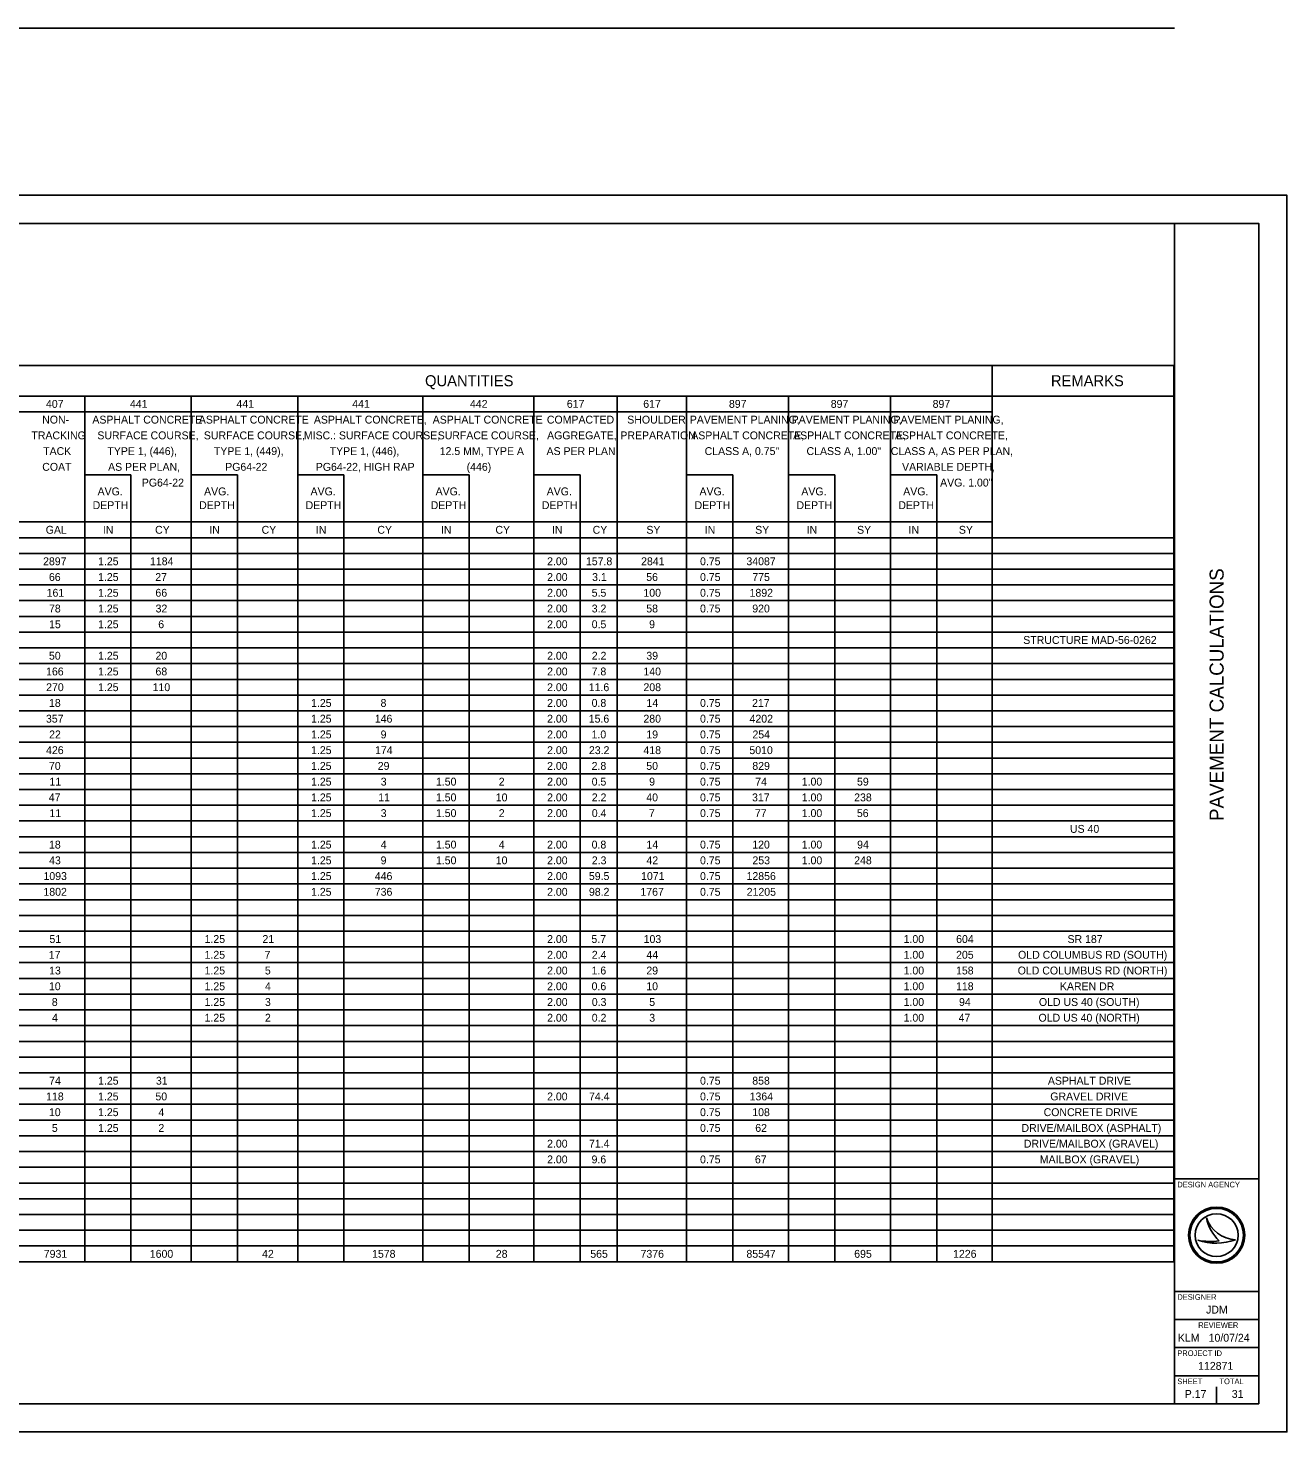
# Model space of a CAD drawing. Extents: x -2.5 to 34, y 0 to 25.
# Drawn here: x 11.61 to 34, y 0 to 24.97 of the extents above; entities that cross this region are included whole.
import ezdxf

# ---------------------------------------------------------------- set-up
doc = ezdxf.new("R2010")
doc.units = 0
for name, color, linetype in [('SH_Border', 7, 'Continuous'), ('SH_Cut_Line', 7, 'Continuous'), ('SH_Data', 7, 'Continuous'), ('SH_Text', 7, 'Continuous')]:
    doc.layers.add(name, color=color, linetype=linetype)

msp = doc.modelspace()

# ---------------------------------------------------------------- linework, layer by layer
at = {"layer": 'SH_Border'}
for p, q in [((32, 0.5), (32, 21.5)), ((32, 4.5), (33.5, 4.5)), ((32, 2.5), (33.5, 2.5)), ((32, 2), (33.5, 2)), ((32, 1.5), (33.5, 1.5)), ((32, 1), (33.5, 1))]:
    msp.add_line(p, q, dxfattribs=at)
msp.add_lwpolyline([(1.5, 21.5), (33.5, 21.5), (33.5, 0.5), (1.5, 0.5)], close=True, dxfattribs=at)
at = {"layer": 'SH_Cut_Line'}
msp.add_lwpolyline([(0, 0), (34, 0), (34, 22), (0, 22)], close=True, dxfattribs=at)
at = {"layer": 'SH_Data'}
for p, q in [((32.567, 3.81), (32.567, 3.81)), ((32.75, 3.5), (32.75, 3.5)), ((32.417, 3.41), (32.417, 3.41)), ((33.087, 3.419), (33.087, 3.419)), ((32.75, 0.5), (32.75, 0.8)), ((32.375, 0.675), (32.375, 0.675))]:
    msp.add_line(p, q, dxfattribs=at)
for radius in [0.5, 0.477, 0.477, 0.382]:
    msp.add_circle((32.75, 3.5), radius, dxfattribs=at)
for centre, radius, start, end in [((33.116, 3.998), 0.58, 198.9257, 198.9319), ((33.347, 3.97), 0.796, 191.6379, 191.6421), ((33.116, 3.998), 0.58, 198.9319, 267.1657), ((33.347, 3.97), 0.796, 191.6421, 226.0947), ((32.739, 4.37), 1.013, 251.4576, 290.0832), ((32.648, 4.654), 1.266, 259.4964, 259.4995), ((32.739, 4.37), 1.013, 251.4527, 251.4576), ((32.648, 4.654), 1.266, 259.4995, 276.6672)]:
    msp.add_arc(centre, radius, start, end, dxfattribs=at)
at = {"layer": 'SH_Text'}
for p, q in [((1.5, 24.973), (32, 24.973)), ((1.5, 18.972), (31.987, 18.972)), ((28.759, 18.972), (28.759, 3.028)), ((31.987, 18.972), (31.987, 3.028)), ((1.5, 18.428), (31.987, 18.428)), ((12.618, 18.428), (12.618, 3.028)), ((14.512, 18.428), (14.512, 3.028)), ((16.406, 18.428), (16.406, 3.028)), ((18.629, 18.428), (18.629, 3.028)), ((20.606, 18.428), (20.606, 3.028)), ((22.088, 18.428), (22.088, 3.028)), ((23.324, 18.428), (23.324, 3.028)), ((25.135, 18.428), (25.135, 3.028)), ((26.947, 18.428), (26.947, 3.028)), ((9.982, 18.148), (28.759, 18.148)), ((12.618, 17.028), (13.441, 17.028)), ((13.441, 17.028), (13.441, 3.028)), ((14.512, 17.028), (15.335, 17.028)), ((15.335, 17.028), (15.335, 3.028)), ((16.406, 17.028), (17.229, 17.028)), ((17.229, 17.028), (17.229, 3.028)), ((18.629, 17.028), (19.453, 17.028)), ((19.453, 17.028), (19.453, 3.028)), ((20.606, 17.028), (21.429, 17.028)), ((21.429, 17.028), (21.429, 3.028)), ((23.324, 17.028), (24.147, 17.028)), ((24.147, 17.028), (24.147, 3.028)), ((25.135, 17.028), (25.959, 17.028)), ((25.959, 17.028), (25.959, 3.028)), ((26.947, 17.028), (27.771, 17.028)), ((27.771, 17.028), (27.771, 3.028)), ((7.759, 16.188), (28.759, 16.188)), ((1.5, 15.908), (31.987, 15.908)), ((1.5, 15.628), (31.987, 15.628)), ((1.5, 15.348), (31.987, 15.348)), ((1.5, 15.068), (31.987, 15.068)), ((1.5, 14.788), (31.987, 14.788)), ((1.5, 14.508), (31.987, 14.508)), ((1.5, 14.228), (31.987, 14.228)), ((1.5, 13.948), (31.987, 13.948)), ((1.5, 13.668), (31.987, 13.668)), ((1.5, 13.388), (31.987, 13.388)), ((1.5, 13.108), (31.987, 13.108)), ((1.5, 12.828), (31.987, 12.828)), ((1.5, 12.548), (31.987, 12.548)), ((1.5, 12.268), (31.987, 12.268)), ((1.5, 11.988), (31.987, 11.988)), ((1.5, 11.708), (31.987, 11.708)), ((1.5, 11.428), (31.987, 11.428)), ((1.5, 11.148), (31.987, 11.148)), ((1.5, 10.868), (31.987, 10.868)), ((1.5, 10.588), (31.987, 10.588)), ((1.5, 10.308), (31.987, 10.308)), ((1.5, 10.028), (31.987, 10.028)), ((1.5, 9.748), (31.987, 9.748)), ((1.5, 9.468), (31.987, 9.468)), ((1.5, 9.188), (31.987, 9.188)), ((1.5, 8.908), (31.987, 8.908)), ((1.5, 8.628), (31.987, 8.628)), ((1.5, 8.348), (31.987, 8.348)), ((1.5, 8.068), (31.987, 8.068)), ((1.5, 7.788), (31.987, 7.788)), ((1.5, 7.508), (31.987, 7.508)), ((1.5, 7.228), (31.987, 7.228)), ((1.5, 6.948), (31.987, 6.948)), ((1.5, 6.668), (31.987, 6.668)), ((1.5, 6.388), (31.987, 6.388)), ((1.5, 6.108), (31.987, 6.108)), ((1.5, 5.828), (31.987, 5.828)), ((1.5, 5.548), (31.987, 5.548)), ((1.5, 5.268), (31.987, 5.268)), ((1.5, 4.988), (31.987, 4.988)), ((1.5, 4.708), (31.987, 4.708)), ((1.5, 4.428), (31.987, 4.428)), ((1.5, 4.148), (31.987, 4.148)), ((1.5, 3.868), (31.987, 3.868)), ((1.5, 3.588), (31.987, 3.588)), ((1.5, 3.308), (31.987, 3.308)), ((1.5, 3.028), (31.987, 3.028))]:
    msp.add_line(p, q, dxfattribs=at)

# ---------------------------------------------------------------- texts
at = {"layer": 'SH_Data'}
msp.add_text('PAVEMENT CALCULATIONS', height=0.25, rotation=90, dxfattribs=at).set_placement((32.875, 10.868))
for s, height, p in [('DESIGN AGENCY', 0.1, (32.05, 4.35)), ('DESIGNER', 0.1, (32.05, 2.35)), ('JDM', 0.14, (32.562, 2.105)), ('REVIEWER', 0.1, (32.422, 1.85)), ('10/07/24', 0.14, (32.608, 1.605)), ('KLM', 0.14, (32.061, 1.605)), ('PROJECT ID', 0.1, (32.05, 1.35)), ('112871', 0.14, (32.421, 1.105)), ('SHEET', 0.1, (32.05, 0.85)), ('TOTAL', 0.1, (32.8, 0.85)), ('P.17', 0.14, (32.183, 0.605)), ('31', 0.14, (33.019, 0.605))]:
    msp.add_text(s, height=height, dxfattribs=at).set_placement(p)
at = {"layer": 'SH_Text'}
for s, height, p in [('QUANTITIES', 0.196, (18.671, 18.602)), ('REMARKS', 0.196, (29.803, 18.602)), ('407', 0.14, (11.929, 18.218)), ('441', 0.14, (13.423, 18.218)), ('441', 0.14, (15.317, 18.218)), ('441', 0.14, (17.376, 18.218)), ('442', 0.14, (19.47, 18.218)), ('617', 0.14, (21.193, 18.218)), ('617', 0.14, (22.552, 18.218)), ('897', 0.14, (24.076, 18.218)), ('897', 0.14, (25.887, 18.218)), ('897', 0.14, (27.699, 18.218)), ('NON-', 0.14, (11.862, 17.938)), ('ASPHALT CONCRETE', 0.14, (12.754, 17.938)), ('ASPHALT CONCRETE', 0.14, (14.648, 17.938)), ('ASPHALT CONCRETE,', 0.14, (16.694, 17.938)), ('ASPHALT CONCRETE', 0.14, (18.807, 17.938)), ('COMPACTED', 0.14, (20.838, 17.938)), ('SHOULDER', 0.14, (22.268, 17.938)), ('PAVEMENT PLANING,', 0.14, (23.38, 17.938)), ('PAVEMENT PLANING,', 0.14, (25.192, 17.938)), ('PAVEMENT PLANING,', 0.14, (27.004, 17.938)), ('TRACKING', 0.14, (11.67, 17.658)), ('SURFACE COURSE,', 0.14, (12.843, 17.658)), ('SURFACE COURSE,', 0.14, (14.737, 17.658)), ('MISC.: SURFACE COURSE,', 0.14, (16.516, 17.658)), ('SURFACE COURSE,', 0.14, (18.896, 17.658)), ('AGGREGATE,', 0.14, (20.842, 17.658)), ('PREPARATION', 0.14, (22.145, 17.658)), ('ASPHALT CONCRETE,', 0.14, (23.406, 17.658)), ('ASPHALT CONCRETE,', 0.14, (25.218, 17.658)), ('ASPHALT CONCRETE,', 0.14, (27.029, 17.658)), ('TACK', 0.14, (11.879, 17.378)), ('TYPE 1, (446),', 0.14, (13.022, 17.378)), ('TYPE 1, (449),', 0.14, (14.916, 17.378)), ('TYPE 1, (446),', 0.14, (16.975, 17.378)), ('12.5 MM, TYPE A', 0.14, (18.932, 17.378)), ('AS PER PLAN', 0.14, (20.832, 17.378)), ('CLASS A, 0.75"', 0.14, (23.644, 17.378)), ('CLASS A, 1.00"', 0.14, (25.456, 17.378)), ('CLASS A, AS PER PLAN,', 0.14, (26.955, 17.378)), ('COAT', 0.14, (11.863, 17.098)), ('AS PER PLAN,', 0.14, (13.034, 17.098)), ('PG64-22', 0.14, (15.117, 17.098)), ('PG64-22, HIGH RAP', 0.14, (16.728, 17.098)), ('(446)', 0.14, (19.411, 17.098)), ('VARIABLE DEPTH,', 0.14, (27.155, 17.098)), ('AVG. ', 0.14, (12.847, 16.661)), ('PG64-22', 0.14, (13.634, 16.818)), ('AVG. ', 0.14, (14.741, 16.661)), ('AVG. ', 0.14, (16.635, 16.661)), ('AVG. ', 0.14, (18.859, 16.661)), ('AVG. ', 0.14, (20.835, 16.661)), ('AVG. ', 0.14, (23.553, 16.661)), ('AVG. ', 0.14, (25.364, 16.661)), ('AVG. ', 0.14, (27.176, 16.661)), ('AVG. 1.00"', 0.14, (27.832, 16.818)), ('DEPTH', 0.14, (12.759, 16.416)), ('DEPTH', 0.14, (14.653, 16.416)), ('DEPTH', 0.14, (16.547, 16.416)), ('DEPTH', 0.14, (18.771, 16.416)), ('DEPTH', 0.14, (20.748, 16.416)), ('DEPTH', 0.14, (23.465, 16.416)), ('DEPTH', 0.14, (25.277, 16.416)), ('DEPTH', 0.14, (27.089, 16.416)), ('GAL', 0.14, (11.925, 15.978)), ('IN', 0.14, (12.941, 15.978)), ('CY', 0.14, (13.87, 15.978)), ('IN', 0.14, (14.835, 15.978)), ('CY', 0.14, (15.764, 15.978)), ('IN', 0.14, (16.729, 15.978)), ('CY', 0.14, (17.823, 15.978)), ('IN', 0.14, (18.953, 15.978)), ('CY', 0.14, (19.923, 15.978)), ('IN', 0.14, (20.929, 15.978)), ('CY', 0.14, (21.652, 15.978)), ('SY', 0.14, (22.608, 15.978)), ('IN', 0.14, (23.647, 15.978)), ('SY', 0.14, (24.543, 15.978)), ('IN', 0.14, (25.459, 15.978)), ('SY', 0.14, (26.355, 15.978)), ('IN', 0.14, (27.27, 15.978)), ('SY', 0.14, (28.166, 15.978)), ('2897', 0.14, (11.878, 15.418)), ('1.25', 0.14, (12.856, 15.418)), ('1184', 0.14, (13.779, 15.418)), ('2.00', 0.14, (20.842, 15.418)), ('157.8', 0.14, (21.533, 15.418)), ('2841', 0.14, (22.514, 15.418)), ('0.75', 0.14, (23.562, 15.418)), ('34087', 0.14, (24.387, 15.418)), ('66', 0.14, (11.982, 15.138)), ('1.25', 0.14, (12.856, 15.138)), ('27', 0.14, (13.873, 15.138)), ('2.00', 0.14, (20.842, 15.138)), ('3.1', 0.14, (21.642, 15.138)), ('56', 0.14, (22.605, 15.138)), ('0.75', 0.14, (23.562, 15.138)), ('775', 0.14, (24.492, 15.138)), ('161', 0.14, (11.941, 14.858)), ('1.25', 0.14, (12.856, 14.858)), ('66', 0.14, (13.876, 14.858)), ('2.00', 0.14, (20.842, 14.858)), ('5.5', 0.14, (21.635, 14.858)), ('100', 0.14, (22.555, 14.858)), ('0.75', 0.14, (23.562, 14.858)), ('1892', 0.14, (24.443, 14.858)), ('78', 0.14, (11.983, 14.578)), ('1.25', 0.14, (12.856, 14.578)), ('32', 0.14, (13.879, 14.578)), ('2.00', 0.14, (20.842, 14.578)), ('3.2', 0.14, (21.636, 14.578)), ('58', 0.14, (22.606, 14.578)), ('0.75', 0.14, (23.562, 14.578)), ('920', 0.14, (24.491, 14.578)), ('15', 0.14, (11.984, 14.298)), ('1.25', 0.14, (12.856, 14.298)), ('6', 0.14, (13.926, 14.298)), ('2.00', 0.14, (20.842, 14.298)), ('0.5', 0.14, (21.635, 14.298)), ('9', 0.14, (22.657, 14.298)), ('STRUCTURE MAD-56-0262', 0.14, (29.311, 14.018)), ('50', 0.14, (11.982, 13.738)), ('1.25', 0.14, (12.856, 13.738)), ('20', 0.14, (13.876, 13.738)), ('2.00', 0.14, (20.842, 13.738)), ('2.2', 0.14, (21.636, 13.738)), ('39', 0.14, (22.607, 13.738)), ('166', 0.14, (11.931, 13.458)), ('1.25', 0.14, (12.856, 13.458)), ('68', 0.14, (13.877, 13.458)), ('2.00', 0.14, (20.842, 13.458)), ('7.8', 0.14, (21.634, 13.458)), ('140', 0.14, (22.555, 13.458)), ('270', 0.14, (11.932, 13.178)), ('1.25', 0.14, (12.856, 13.178)), ('110', 0.14, (13.826, 13.178)), ('2.00', 0.14, (20.842, 13.178)), ('11.6', 0.14, (21.583, 13.178)), ('208', 0.14, (22.556, 13.178)), ('18', 0.14, (11.983, 12.898)), ('1.25', 0.14, (16.644, 12.898)), ('8', 0.14, (17.88, 12.898)), ('2.00', 0.14, (20.842, 12.898)), ('0.8', 0.14, (21.634, 12.898)), ('14', 0.14, (22.609, 12.898)), ('0.75', 0.14, (23.562, 12.898)), ('217', 0.14, (24.487, 12.898)), ('357', 0.14, (11.929, 12.618)), ('1.25', 0.14, (16.644, 12.618)), ('146', 0.14, (17.778, 12.618)), ('2.00', 0.14, (20.842, 12.618)), ('15.6', 0.14, (21.583, 12.618)), ('280', 0.14, (22.555, 12.618)), ('0.75', 0.14, (23.562, 12.618)), ('4202', 0.14, (24.443, 12.618)), ('22', 0.14, (11.985, 12.338)), ('1.25', 0.14, (16.644, 12.338)), ('9', 0.14, (17.881, 12.338)), ('2.00', 0.14, (20.842, 12.338)), ('1.0', 0.14, (21.633, 12.338)), ('19', 0.14, (22.607, 12.338)), ('0.75', 0.14, (23.562, 12.338)), ('254', 0.14, (24.494, 12.338)), ('426', 0.14, (11.931, 12.058)), ('1.25', 0.14, (16.644, 12.058)), ('174', 0.14, (17.782, 12.058)), ('2.00', 0.14, (20.842, 12.058)), ('23.2', 0.14, (21.586, 12.058)), ('418', 0.14, (22.556, 12.058)), ('0.75', 0.14, (23.562, 12.058)), ('5010', 0.14, (24.44, 12.058)), ('70', 0.14, (11.982, 11.778)), ('1.25', 0.14, (16.644, 11.778)), ('29', 0.14, (17.83, 11.778)), ('2.00', 0.14, (20.842, 11.778)), ('2.8', 0.14, (21.634, 11.778)), ('50', 0.14, (22.606, 11.778)), ('0.75', 0.14, (23.562, 11.778)), ('829', 0.14, (24.492, 11.778)), ('11', 0.14, (11.991, 11.498)), ('1.25', 0.14, (16.644, 11.498)), ('3', 0.14, (17.883, 11.498)), ('1.50', 0.14, (18.865, 11.498)), ('2', 0.14, (19.982, 11.498)), ('2.00', 0.14, (20.842, 11.498)), ('0.5', 0.14, (21.635, 11.498)), ('9', 0.14, (22.657, 11.498)), ('0.75', 0.14, (23.562, 11.498)), ('74', 0.14, (24.544, 11.498)), ('1.00', 0.14, (25.371, 11.498)), ('59', 0.14, (26.354, 11.498)), ('47', 0.14, (11.979, 11.218)), ('1.25', 0.14, (16.644, 11.218)), ('11', 0.14, (17.838, 11.218)), ('1.50', 0.14, (18.865, 11.218)), ('10', 0.14, (19.929, 11.218)), ('2.00', 0.14, (20.842, 11.218)), ('2.2', 0.14, (21.636, 11.218)), ('40', 0.14, (22.606, 11.218)), ('0.75', 0.14, (23.562, 11.218)), ('317', 0.14, (24.487, 11.218)), ('1.00', 0.14, (25.371, 11.218)), ('238', 0.14, (26.303, 11.218)), ('11', 0.14, (11.991, 10.938)), ('1.25', 0.14, (16.644, 10.938)), ('3', 0.14, (17.883, 10.938)), ('1.50', 0.14, (18.865, 10.938)), ('2', 0.14, (19.982, 10.938)), ('2.00', 0.14, (20.842, 10.938)), ('0.4', 0.14, (21.637, 10.938)), ('7', 0.14, (22.653, 10.938)), ('0.75', 0.14, (23.562, 10.938)), ('77', 0.14, (24.538, 10.938)), ('1.00', 0.14, (25.371, 10.938)), ('56', 0.14, (26.352, 10.938)), ('US 40', 0.14, (30.142, 10.658)), ('18', 0.14, (11.983, 10.378)), ('1.25', 0.14, (16.644, 10.378)), ('4', 0.14, (17.883, 10.378)), ('1.50', 0.14, (18.865, 10.378)), ('4', 0.14, (19.983, 10.378)), ('2.00', 0.14, (20.842, 10.378)), ('0.8', 0.14, (21.634, 10.378)), ('14', 0.14, (22.609, 10.378)), ('0.75', 0.14, (23.562, 10.378)), ('120', 0.14, (24.491, 10.378)), ('1.00', 0.14, (25.371, 10.378)), ('94', 0.14, (26.356, 10.378)), ('43', 0.14, (11.985, 10.098)), ('1.25', 0.14, (16.644, 10.098)), ('9', 0.14, (17.881, 10.098)), ('1.50', 0.14, (18.865, 10.098)), ('10', 0.14, (19.929, 10.098)), ('2.00', 0.14, (20.842, 10.098)), ('2.3', 0.14, (21.637, 10.098)), ('42', 0.14, (22.609, 10.098)), ('0.75', 0.14, (23.562, 10.098)), ('253', 0.14, (24.494, 10.098)), ('1.00', 0.14, (25.371, 10.098)), ('248', 0.14, (26.303, 10.098)), ('1093', 0.14, (11.885, 9.818)), ('1.25', 0.14, (16.644, 9.818)), ('446', 0.14, (17.778, 9.818)), ('2.00', 0.14, (20.842, 9.818)), ('59.5', 0.14, (21.585, 9.818)), ('1071', 0.14, (22.514, 9.818)), ('0.75', 0.14, (23.562, 9.818)), ('12856', 0.14, (24.389, 9.818)), ('1802', 0.14, (11.884, 9.538)), ('1.25', 0.14, (16.644, 9.538)), ('736', 0.14, (17.778, 9.538)), ('2.00', 0.14, (20.842, 9.538)), ('98.2', 0.14, (21.586, 9.538)), ('1767', 0.14, (22.502, 9.538)), ('0.75', 0.14, (23.562, 9.538)), ('21205', 0.14, (24.392, 9.538)), ('51', 0.14, (11.991, 8.698)), ('1.25', 0.14, (14.75, 8.698)), ('21', 0.14, (15.779, 8.698)), ('2.00', 0.14, (20.842, 8.698)), ('5.7', 0.14, (21.63, 8.698)), ('103', 0.14, (22.559, 8.698)), ('1.00', 0.14, (27.183, 8.698)), ('604', 0.14, (28.117, 8.698)), ('SR 187', 0.14, (30.098, 8.698)), ('17', 0.14, (11.979, 8.418)), ('1.25', 0.14, (14.75, 8.418)), ('7', 0.14, (15.817, 8.418)), ('2.00', 0.14, (20.842, 8.418)), ('2.4', 0.14, (21.637, 8.418)), ('44', 0.14, (22.609, 8.418)), ('1.00', 0.14, (27.183, 8.418)), ('205', 0.14, (28.116, 8.418)), ('OLD COLUMBUS RD (SOUTH)', 0.14, (29.219, 8.418)), ('13', 0.14, (11.985, 8.138)), ('1.25', 0.14, (14.75, 8.138)), ('5', 0.14, (15.822, 8.138)), ('2.00', 0.14, (20.842, 8.138)), ('1.6', 0.14, (21.633, 8.138)), ('29', 0.14, (22.607, 8.138)), ('1.00', 0.14, (27.183, 8.138)), ('158', 0.14, (28.115, 8.138)), ('OLD COLUMBUS RD (NORTH)', 0.14, (29.212, 8.138)), ('10', 0.14, (11.982, 7.858)), ('1.25', 0.14, (14.75, 7.858)), ('4', 0.14, (15.824, 7.858)), ('2.00', 0.14, (20.842, 7.858)), ('0.6', 0.14, (21.633, 7.858)), ('10', 0.14, (22.606, 7.858)), ('1.00', 0.14, (27.183, 7.858)), ('118', 0.14, (28.115, 7.858)), ('KAREN DR', 0.14, (29.963, 7.858)), ('8', 0.14, (12.033, 7.578)), ('1.25', 0.14, (14.75, 7.578)), ('3', 0.14, (15.824, 7.578)), ('2.00', 0.14, (20.842, 7.578)), ('0.3', 0.14, (21.637, 7.578)), ('5', 0.14, (22.658, 7.578)), ('1.00', 0.14, (27.183, 7.578)), ('94', 0.14, (28.168, 7.578)), ('OLD US 40 (SOUTH)', 0.14, (29.589, 7.578)), ('4', 0.14, (12.036, 7.298)), ('1.25', 0.14, (14.75, 7.298)), ('2', 0.14, (15.824, 7.298)), ('2.00', 0.14, (20.842, 7.298)), ('0.2', 0.14, (21.636, 7.298)), ('3', 0.14, (22.659, 7.298)), ('1.00', 0.14, (27.183, 7.298)), ('47', 0.14, (28.161, 7.298)), ('OLD US 40 (NORTH)', 0.14, (29.582, 7.298)), ('74', 0.14, (11.985, 6.178)), ('1.25', 0.14, (12.856, 6.178)), ('31', 0.14, (13.885, 6.178)), ('0.75', 0.14, (23.562, 6.178)), ('858', 0.14, (24.491, 6.178)), ('ASPHALT DRIVE', 0.14, (29.749, 6.178)), ('118', 0.14, (11.932, 5.898)), ('1.25', 0.14, (12.856, 5.898)), ('50', 0.14, (13.876, 5.898)), ('2.00', 0.14, (20.842, 5.898)), ('74.4', 0.14, (21.587, 5.898)), ('0.75', 0.14, (23.562, 5.898)), ('1364', 0.14, (24.444, 5.898)), ('GRAVEL DRIVE', 0.14, (29.791, 5.898)), ('10', 0.14, (11.982, 5.618)), ('1.25', 0.14, (12.856, 5.618)), ('4', 0.14, (13.93, 5.618)), ('0.75', 0.14, (23.562, 5.618)), ('108', 0.14, (24.491, 5.618)), ('CONCRETE DRIVE', 0.14, (29.673, 5.618)), ('5', 0.14, (12.034, 5.338)), ('1.25', 0.14, (12.856, 5.338)), ('2', 0.14, (13.929, 5.338)), ('0.75', 0.14, (23.562, 5.338)), ('62', 0.14, (24.544, 5.338)), ('DRIVE/MAILBOX (ASPHALT)', 0.14, (29.279, 5.338)), ('2.00', 0.14, (20.842, 5.058)), ('71.4', 0.14, (21.587, 5.058)), ('DRIVE/MAILBOX (GRAVEL)', 0.14, (29.321, 5.058)), ('2.00', 0.14, (20.842, 4.778)), ('9.6', 0.14, (21.633, 4.778)), ('0.75', 0.14, (23.562, 4.778)), ('67', 0.14, (24.538, 4.778)), ('MAILBOX (GRAVEL)', 0.14, (29.605, 4.778)), ('7931', 0.14, (11.89, 3.098)), ('1600', 0.14, (13.776, 3.098)), ('42', 0.14, (15.773, 3.098)), ('1578', 0.14, (17.729, 3.098)), ('28', 0.14, (19.93, 3.098)), ('565', 0.14, (21.61, 3.098)), ('7376', 0.14, (22.504, 3.098)), ('85547', 0.14, (24.387, 3.098)), ('695', 0.14, (26.304, 3.098)), ('1226', 0.14, (28.063, 3.098))]:
    msp.add_text(s, height=height, dxfattribs=at).set_placement(p)

doc.saveas('drawing.dxf')
